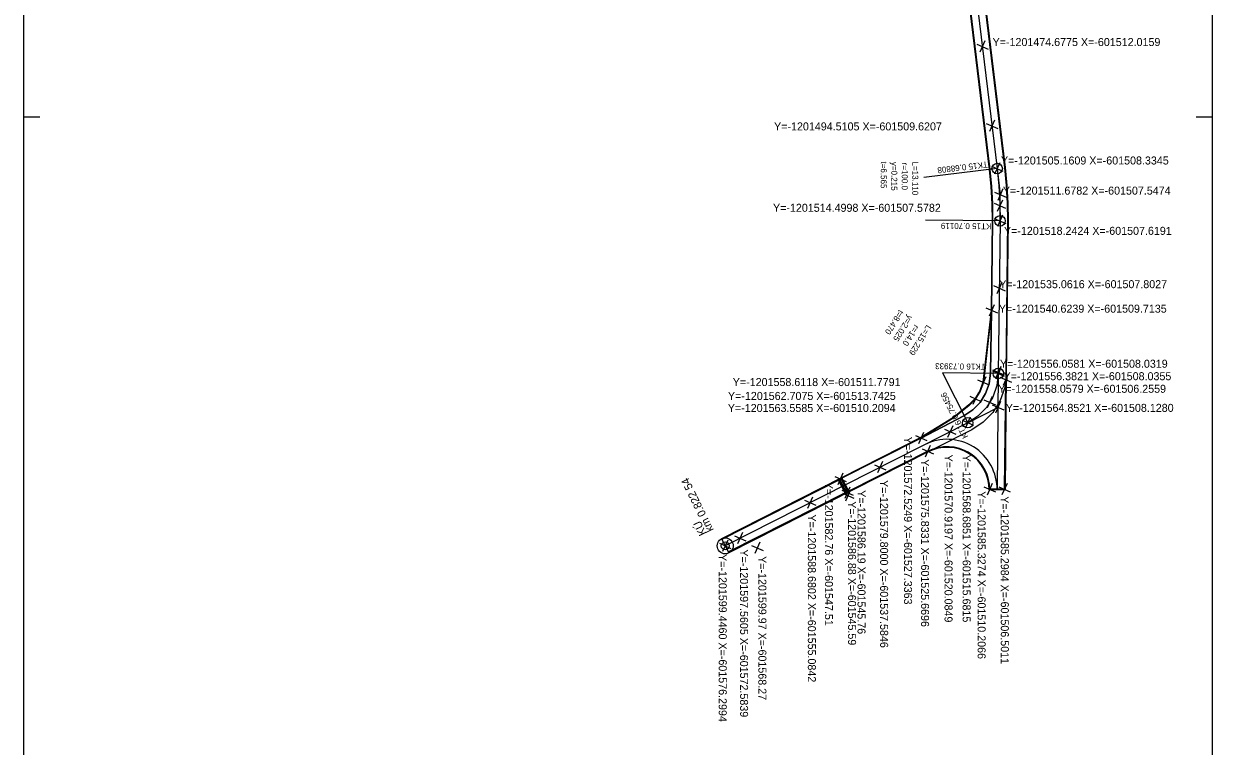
# Model space of a CAD drawing. Extents: x -601752 to -601455, y -1201912 to -1200862.
# Drawn here: x -601751.6 to -601454.6, y -1201649.5 to -1201469 of the extents above; entities that cross this region are included whole.
import ezdxf

# ---------------------------------------------------------------- set-up
doc = ezdxf.new("R2010")
doc.units = 0
for name, color, linetype in [('g_vytyceni oblouky', 7, 'Continuous'), ('g_vytyceni prejezd', 7, 'Continuous'), ('g_vytyceni příčné', 7, 'Continuous'), ('q_vytyceni prahy souradnice', 7, 'Continuous'), ('u_návrh', 7, 'Continuous'), ('u_oblouky', 7, 'Continuous'), ('u_osa', 7, 'Continuous'), ('u_popis', 7, 'Continuous'), ('u_popis oblouky', 7, 'Continuous'), ('u_příčný odvodňovací žlab', 7, 'Continuous'), ('u_rozšíření v obloucích', 7, 'Continuous'), ('u_staniceni', 7, 'Continuous'), ('x_rám', 7, 'Continuous')]:
    doc.layers.add(name, color=color, linetype=linetype)

msp = doc.modelspace()

# ---------------------------------------------------------------- linework, layer by layer
at = {"layer": 'g_vytyceni oblouky'}
for p, q in [((-601509.76, -1201504.53), (-601506.91, -1201505.79)), ((-601507.7, -1201503.73), (-601508.97, -1201506.59)), ((-601506.91, -1201510.25), (-601508.18, -1201513.11)), ((-601508.98, -1201511.05), (-601506.12, -1201512.31)), ((-601509.05, -1201517.61), (-601506.19, -1201518.87)), ((-601506.99, -1201516.81), (-601508.25, -1201519.67)), ((-601507.4, -1201554.95), (-601508.67, -1201557.81)), ((-601509.46, -1201555.75), (-601506.61, -1201557.01)), ((-601511.64, -1201562.93), (-601508.78, -1201564.19)), ((-601509.58, -1201562.13), (-601510.84, -1201564.99)), ((-601507.5, -1201563.42), (-601508.76, -1201566.28)), ((-601509.56, -1201564.22), (-601506.7, -1201565.48)), ((-601517.11, -1201568.05), (-601514.25, -1201569.32)), ((-601515.05, -1201567.26), (-601516.31, -1201570.11))]:
    msp.add_line(p, q, dxfattribs=at)
at = {"layer": 'g_vytyceni prejezd'}
for p, q in [((-601511.14, -1201539.99), (-601508.28, -1201541.26)), ((-601509.08, -1201539.2), (-601510.35, -1201542.05)), ((-601513.21, -1201557.98), (-601510.35, -1201559.24)), ((-601511.15, -1201557.18), (-601512.41, -1201560.04)), ((-601507.64, -1201557.32), (-601504.78, -1201558.59)), ((-601505.58, -1201556.53), (-601506.84, -1201559.39)), ((-601515.17, -1201562.08), (-601512.31, -1201563.34)), ((-601513.11, -1201561.28), (-601514.38, -1201564.14)), ((-601528.77, -1201571.89), (-601525.91, -1201573.16)), ((-601526.7, -1201571.1), (-601527.97, -1201573.95)), ((-601527.1, -1201575.2), (-601524.24, -1201576.47)), ((-601525.04, -1201574.4), (-601526.3, -1201577.26)), ((-601511.64, -1201584.69), (-601508.78, -1201585.96)), ((-601509.57, -1201583.9), (-601510.84, -1201586.76)), ((-601507.93, -1201584.67), (-601505.07, -1201585.93)), ((-601505.87, -1201583.87), (-601507.13, -1201586.73))]:
    msp.add_line(p, q, dxfattribs=at)
at = {"layer": 'g_vytyceni příčné'}
for p, q in [((-601513.44, -1201474.05), (-601510.59, -1201475.31)), ((-601511.38, -1201473.25), (-601512.65, -1201476.11)), ((-601511.05, -1201493.88), (-601508.19, -1201495.14)), ((-601508.99, -1201493.08), (-601510.25, -1201495.94)), ((-601507.03, -1201513.03), (-601508.29, -1201515.89)), ((-601509.09, -1201513.83), (-601506.23, -1201515.1)), ((-601507.17, -1201533.63), (-601508.44, -1201536.49)), ((-601509.23, -1201534.43), (-601506.37, -1201535.69)), ((-601507.4, -1201554.63), (-601508.66, -1201557.49)), ((-601509.46, -1201555.43), (-601506.6, -1201556.69)), ((-601519.45, -1201569.49), (-601520.72, -1201572.35)), ((-601521.51, -1201570.29), (-601518.66, -1201571.55)), ((-601536.95, -1201578.37), (-601538.22, -1201581.23)), ((-601539.01, -1201579.17), (-601536.16, -1201580.43)), ((-601554.45, -1201587.25), (-601555.72, -1201590.11)), ((-601547.02, -1201586.25), (-601544.16, -1201587.51)), ((-601544.96, -1201585.45), (-601546.23, -1201588.31)), ((-601556.51, -1201588.05), (-601553.66, -1201589.31)), ((-601571.95, -1201596.13), (-601573.22, -1201598.99)), ((-601577.73, -1201598.81), (-601574.87, -1201600.08)), ((-601575.67, -1201598.02), (-601576.93, -1201600.87)), ((-601574.01, -1201596.93), (-601571.16, -1201598.19)), ((-601569.7, -1201599.34), (-601566.84, -1201600.6)), ((-601567.64, -1201598.54), (-601568.9, -1201601.4))]:
    msp.add_line(p, q, dxfattribs=at)
at = {"layer": 'q_vytyceni prahy souradnice'}
for p, q in [((-601546.86, -1201581.32), (-601548.13, -1201584.18)), ((-601548.92, -1201582.12), (-601546.06, -1201583.39)), ((-601545.12, -1201584.76), (-601546.39, -1201587.62)), ((-601547.18, -1201585.56), (-601544.33, -1201586.82))]:
    msp.add_line(p, q, dxfattribs=at)
at = {"layer": 'u_návrh'}
for p, q in [((-601506.04, -1201556.51), (-601506.35, -1201585.45)), ((-601506.35, -1201585.45), (-601510.36, -1201585.48)), ((-601577.24, -1201597.68), (-601575.36, -1201601.21))]:
    msp.add_line(p, q, dxfattribs=at)
for points in [[(-601549.75, -1201316.3), (-601549.39, -1201317.23), (-601542.68, -1201332.11), (-601535.16, -1201346.59), (-601526.84, -1201360.67), (-601522.55, -1201367.52), (-601519.89, -1201372.13), (-601517.56, -1201376.95), (-601515.6, -1201381.93), (-601514.03, -1201387.02), (-601512.87, -1201391.36), (-601511.61, -1201396.91), (-601510.79, -1201402.59), (-601510.43, -1201408.32), (-601510.53, -1201414.01), (-601512.26, -1201444.39), (-601512.42, -1201450.21), (-601512.24, -1201456), (-601511.71, -1201461.79), (-601506.5, -1201504.96), (-601506.06, -1201509.37), (-601505.82, -1201513.81), (-601505.77, -1201518.24), (-601506.19, -1201556.5)], [(-601553.14, -1201317.8), (-601552.81, -1201318.66), (-601546.01, -1201333.72), (-601538.39, -1201348.39), (-601530, -1201362.6), (-601525.72, -1201369.43), (-601523.16, -1201373.86), (-601520.96, -1201378.43), (-601519.1, -1201383.16), (-601517.59, -1201388.04), (-601516.46, -1201392.25), (-601515.25, -1201397.59), (-601514.48, -1201402.97), (-601514.13, -1201408.4), (-601514.23, -1201413.88), (-601515.96, -1201444.23), (-601516.12, -1201450.21), (-601515.93, -1201456.22), (-601515.39, -1201462.18), (-601510.17, -1201505.36), (-601509.75, -1201509.65), (-601509.52, -1201513.93), (-601509.47, -1201518.24), (-601509.71, -1201540.62)], [(-601515.54, -1201462.2), (-601510.32, -1201505.38), (-601509.9, -1201509.66), (-601509.67, -1201513.94), (-601509.62, -1201518.24), (-601509.86, -1201540.61)], [(-601511.56, -1201461.78), (-601506.35, -1201504.94), (-601505.91, -1201509.36), (-601505.67, -1201513.81), (-601505.62, -1201518.24), (-601506.04, -1201556.51)], [(-601509.86, -1201540.61), (-601511.93, -1201558.58), (-601512.67, -1201560.7), (-601513.86, -1201562.61), (-601515.44, -1201564.22), (-601519.25, -1201567.35), (-601527.41, -1201572.39)], [(-601509.71, -1201540.62), (-601510.03, -1201556.25), (-601510.36, -1201558.94), (-601511.22, -1201561.4), (-601512.59, -1201563.61), (-601514.41, -1201565.47), (-601516.68, -1201566.95), (-601527.34, -1201572.52)], [(-601506.2, -1201557.88), (-601506.44, -1201559.86), (-601507.59, -1201563.14), (-601509.43, -1201566.09), (-601511.86, -1201568.58), (-601514.68, -1201570.42), (-601524.04, -1201575.17)], [(-601527.41, -1201572.39), (-601577.23, -1201597.68)], [(-601527.34, -1201572.52), (-601547.96, -1201582.99)], [(-601525.67, -1201575.83), (-601545.37, -1201585.82)], [(-601525.6, -1201575.97), (-601575.36, -1201601.21)], [(-601547.91, -1201583.08), (-601577.12, -1201597.9)], [(-601546.33, -1201586.2), (-601575.48, -1201600.99)]]:
    msp.add_lwpolyline(points, dxfattribs=at)
msp.add_arc((-601520.85, -1201585.33), 10.5, 359.1692, 116.9057, dxfattribs=at)
at = {"layer": 'u_oblouky'}
for p, q in [((-601508.33, -1201505.16), (-601526.67, -1201507.37)), ((-601508.33, -1201505.16), (-601507.55, -1201511.68)), ((-601507.62, -1201518.24), (-601507.55, -1201511.68)), ((-601507.62, -1201518.24), (-601526.27, -1201518.04)), ((-601508.04, -1201556.38), (-601522, -1201556.23)), ((-601522, -1201556.23), (-601515.68, -1201568.69)), ((-601515.68, -1201568.69), (-601508.13, -1201564.85))]:
    msp.add_line(p, q, dxfattribs=at)
for centre in [(-601508.33, -1201505.16), (-601507.62, -1201518.24), (-601508.04, -1201556.38), (-601515.68, -1201568.69)]:
    msp.add_circle(centre, 1.31, dxfattribs=at)
at = {"layer": 'u_osa'}
msp.add_line((-601508.04, -1201556.38), (-601508.35, -1201585.46), dxfattribs=at)
msp.add_lwpolyline([(-601513.55, -1201461.99), (-601508.33, -1201505.16), (-601507.91, -1201509.51), (-601507.67, -1201513.87), (-601507.62, -1201518.24), (-601508.04, -1201556.38), (-601508.4, -1201559.4), (-601509.41, -1201562.27), (-601511.01, -1201564.85), (-601513.14, -1201567.02), (-601515.68, -1201568.69), (-601576.3, -1201599.45)], dxfattribs=at)
msp.add_arc((-601520.85, -1201585.33), 12.5, 359.3745, 116.9057, dxfattribs=at)
at = {"layer": 'u_příčný odvodňovací žlab'}
for points in [[(-601546.22, -1201586.43), (-601547.12, -1201584.64), (-601548.03, -1201582.86)], [(-601545.99, -1201586.31), (-601546.9, -1201584.53), (-601547.74, -1201582.88)], [(-601545.9, -1201586.27), (-601546.81, -1201584.48), (-601547.65, -1201582.83)], [(-601545.61, -1201586.12), (-601546.52, -1201584.33), (-601547.35, -1201582.68)], [(-601545.52, -1201586.07), (-601546.43, -1201584.29), (-601547.26, -1201582.64)], [(-601545.3, -1201585.96), (-601546.2, -1201584.17), (-601547.04, -1201582.52)]]:
    msp.add_lwpolyline(points, dxfattribs=at)
at = {"layer": 'u_rozšíření v obloucích'}
for p, q in [((-601506.19, -1201556.5), (-601506.5, -1201585.3)), ((-601506.5, -1201585.3), (-601510.21, -1201585.33))]:
    msp.add_line(p, q, dxfattribs=at)
for points in [[(-601509.71, -1201540.62), (-601511.78, -1201558.61), (-601512.54, -1201560.77), (-601513.74, -1201562.71), (-601515.33, -1201564.34), (-601519.16, -1201567.48), (-601527.34, -1201572.52)], [(-601509.71, -1201540.62), (-601511.78, -1201558.61), (-601512.54, -1201560.77), (-601513.74, -1201562.71), (-601515.33, -1201564.34), (-601519.16, -1201567.48), (-601527.34, -1201572.52), (-601516.68, -1201566.95), (-601514.41, -1201565.47), (-601512.59, -1201563.61), (-601511.22, -1201561.4), (-601510.36, -1201558.94), (-601510.03, -1201556.25), (-601509.71, -1201540.62)], [(-601510.21, -1201585.33), (-601506.5, -1201585.3), (-601506.2, -1201557.88), (-601506.44, -1201559.86), (-601507.59, -1201563.14), (-601509.43, -1201566.09), (-601511.86, -1201568.58), (-601514.68, -1201570.42), (-601524.04, -1201575.17)]]:
    msp.add_lwpolyline(points, dxfattribs=at)
for end in [116.9057, 107.4176]:
    msp.add_arc((-601520.85, -1201585.33), 10.65, 359.9947, end, dxfattribs=at)
at = {"layer": 'u_staniceni'}
for radius in [2, 1]:
    msp.add_circle((-601576.3, -1201599.45), radius, dxfattribs=at)
at = {"layer": 'x_rám'}
for p, q in [((-601747.54, -1201492.35), (-601751.58, -1201492.35)), ((-601454.58, -1201492.35), (-601458.63, -1201492.35))]:
    msp.add_line(p, q, dxfattribs=at)
msp.add_lwpolyline([(-601454.58, -1200862.35), (-601454.58, -1201912.35), (-601751.58, -1201912.35), (-601751.58, -1200862.35)], close=True, dxfattribs=at)

# ---------------------------------------------------------------- texts
at = {"layer": 'g_vytyceni oblouky'}
for s, p in [('Y=-1201505.1609 X=-601508.3345', (-601507.39, -1201504.15)), ('Y=-1201511.6782 X=-601507.5474', (-601506.92, -1201511.68)), ('Y=-1201518.2424 X=-601507.6191', (-601506.64, -1201521.73)), ('Y=-1201556.3821 X=-601508.0355', (-601506.74, -1201558.06)), ('Y=-1201563.5585 X=-601510.2094', (-601575.64, -1201566)), ('Y=-1201564.8521 X=-601508.1280', (-601506.17, -1201565.97))]:
    msp.add_text(s, height=2, dxfattribs=at).set_placement(p)
msp.add_text('Y=-1201568.6851 X=-601515.6815', height=2, rotation=270, dxfattribs=at).set_placement((-601516.96, -1201576.64))
at = {"layer": 'g_vytyceni prejezd'}
for s, p in [('Y=-1201540.6239 X=-601509.7135', (-601507.9, -1201541.18)), ('Y=-1201558.6118 X=-601511.7791', (-601574.41, -1201559.52)), ('Y=-1201562.7075 X=-601513.7425', (-601575.61, -1201562.99)), ('Y=-1201558.0579 X=-601506.2559', (-601508.07, -1201561.2))]:
    msp.add_text(s, height=2, dxfattribs=at).set_placement(p)
for s, p in [('Y=-1201572.5249 X=-601527.3363', (-601531.6, -1201572.18)), ('Y=-1201575.8331 X=-601525.6696', (-601527.35, -1201577.79)), ('Y=-1201585.3274 X=-601510.2066', (-601513.21, -1201585.8)), ('Y=-1201585.2984 X=-601506.5011', (-601507.42, -1201587.06))]:
    msp.add_text(s, height=2, rotation=270, dxfattribs=at).set_placement(p)
at = {"layer": 'g_vytyceni příčné'}
for s, p in [('Y=-1201474.6775 X=-601512.0159', (-601509.48, -1201474.55)), ('Y=-1201494.5105 X=-601509.6207', (-601564.08, -1201495.63)), ('Y=-1201514.4998 X=-601507.5782', (-601564.35, -1201515.97)), ('Y=-1201535.0616 X=-601507.8027', (-601507.8, -1201535.06)), ('Y=-1201556.0581 X=-601508.0319', (-601507.65, -1201554.94))]:
    msp.add_text(s, height=2, dxfattribs=at).set_placement(p)
for s, p in [('Y=-1201570.9197 X=-601520.0849', (-601521.48, -1201576.65)), ('Y=-1201579.8000 X=-601537.5846', (-601537.58, -1201583.01)), ('Y=-1201588.6802 X=-601555.0842', (-601555.64, -1201591.61)), ('Y=-1201599.4460 X=-601576.2994', (-601577.91, -1201601.51)), ('Y=-1201597.5605 X=-601572.5839', (-601572.58, -1201600.35))]:
    msp.add_text(s, height=2, rotation=270, dxfattribs=at).set_placement(p)
at = {"layer": 'q_vytyceni prahy souradnice'}
for s, p in [('Y=-1201582.76 X=-601547.51', (-601551.37, -1201583.44)), ('Y=-1201586.19 X=-601545.76', (-601543.23, -1201585.54)), ('Y=-1201586.88 X=-601545.59', (-601545.59, -1201588.32)), ('Y=-1201599.97 X=-601568.27', (-601568, -1201602.02))]:
    msp.add_text(s, height=2, rotation=270, dxfattribs=at).set_placement(p)
at = {"layer": 'u_oblouky'}
for s, rotation, p in [('t=6.565', 269.6752, (-601537.39, -1201503.39)), ('y=0.215', 269.6752, (-601534.77, -1201503.49)), ('r=100.0', 269.6752, (-601532.14, -1201503.66)), ('L=13.110', 269.6752, (-601529.52, -1201503.41)), ('t=8.470', 237.5132, (-601532.85, -1201540.34)), ('y=2.025', 237.5132, (-601530.56, -1201541.64)), ('r=14.0', 237.5132, (-601528.98, -1201544.04)), ('L=15.229', 237.5132, (-601525.92, -1201544.12))]:
    msp.add_text(s, height=1.5, rotation=rotation, dxfattribs=at).set_placement(p)
at = {"layer": 'u_popis'}
for s, p in [('km 0.822 54', (-601579.11, -1201595.47)), ('KÚ ', (-601580.9, -1201596.35))]:
    msp.add_text(s, height=2, rotation=116.1248, dxfattribs=at).set_placement(p)
at = {"layer": 'u_popis oblouky'}
for s, rotation, p in [('TK15 0.68808', 186.7628, (-601510.81, -1201503.4)), ('KT15 0.70119', 179.4393, (-601509.79, -1201518.85)), ('TK16 0.73933', 179.158, (-601511.22, -1201553.97)), ('KT16 0.75456', 116.8822, (-601515.52, -1201572.16))]:
    msp.add_text(s, height=1.5, rotation=rotation, dxfattribs=at).set_placement(p)

doc.saveas('drawing.dxf')
